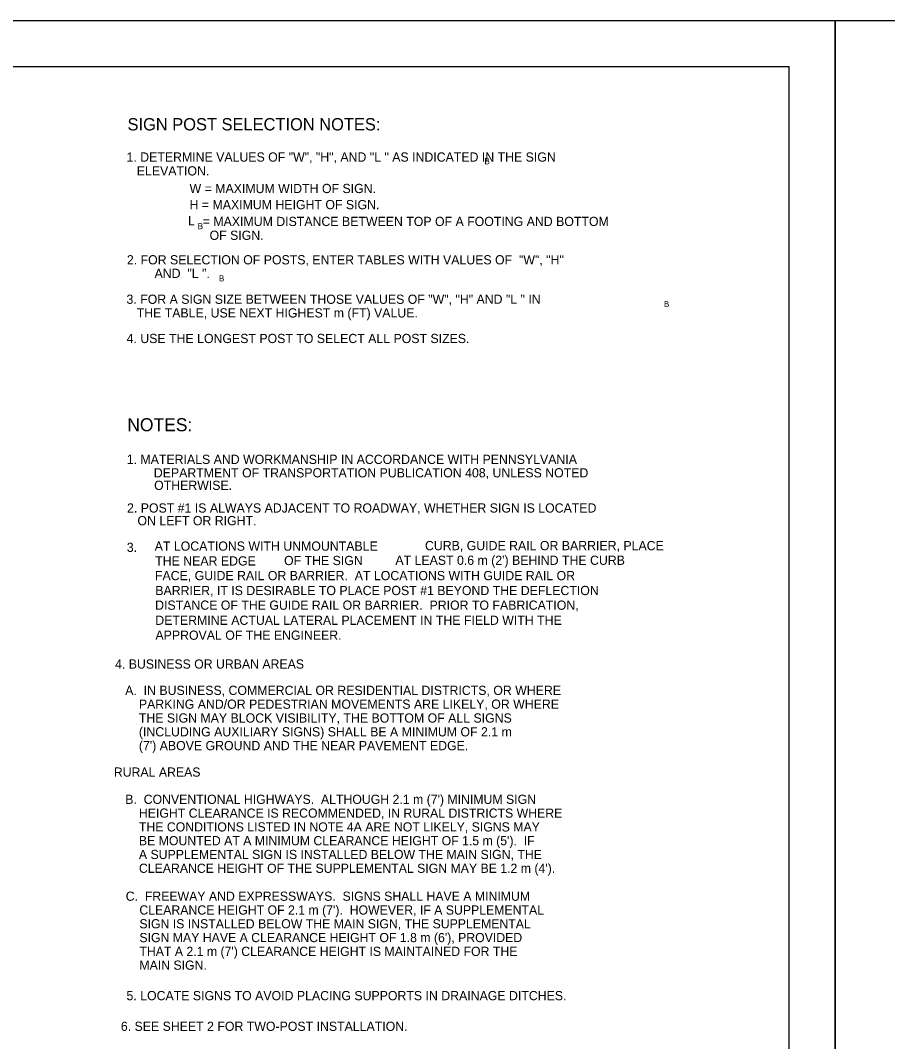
# Model space of a CAD drawing. Extents: x -1958 to 628, y -879 to 309.
# Drawn here: x -1382.9 to -1100.4, y -23.1 to 309.4 of the extents above; entities that cross this region are included whole.
import ezdxf

# ---------------------------------------------------------------- set-up
doc = ezdxf.new("R2010")
doc.units = 0
for name, color, linetype in [('1', 7, 'Continuous'), ('2', 7, 'Continuous'), ('4', 7, 'Continuous'), ('PLT-BNDY', 7, 'Continuous')]:
    doc.layers.add(name, color=color, linetype=linetype)

msp = doc.modelspace()

# ---------------------------------------------------------------- linework, layer by layer
at = {"layer": '1'}
for p in [(-1918.39, 294.44), (-1132.39, -269.56)]:
    msp.add_line(p, (-1132.39, 294.44), dxfattribs=at)
at = {"layer": 'PLT-BNDY'}
for points in [[(-1958.39, 309.44), (-1117.39, 309.44), (-1117.39, -284.56), (-1958.39, -284.56)], [(-1117.39, 309.44), (-276.39, 309.44), (-276.39, -284.56), (-1117.39, -284.56)]]:
    msp.add_lwpolyline(points, close=True, dxfattribs=at)

# ---------------------------------------------------------------- texts
at = {"layer": '1'}
for s, height, p in [('1. DETERMINE VALUES OF "W", "H", AND "L " AS INDICATED IN THE SIGN', 3, (-1348.3, 263.45)), ('B', 2, (-1231.7, 262.61)), ('   ELEVATION.', 3, (-1348.3, 258.95)), ('W = MAXIMUM WIDTH OF SIGN.', 3, (-1327.76, 253.21)), ('H = MAXIMUM HEIGHT OF SIGN.', 3, (-1327.76, 247.96)), ('L', 3, (-1328.26, 242.71)), ('B', 2, (-1325.14, 241.46)), (' = MAXIMUM DISTANCE BETWEEN TOP OF A FOOTING AND BOTTOM', 3, (-1324.59, 242.48)), ('   OF SIGN.', 3, (-1324.59, 237.98)), ('2. FOR SELECTION OF POSTS, ENTER TABLES WITH VALUES OF  "W", "H" ', 3, (-1348.18, 229.99)), ('AND  "L ".', 3, (-1339.17, 225.58)), ('B', 2, (-1318.22, 224.45)), ('3. FOR A SIGN SIZE BETWEEN THOSE VALUES OF "W", "H" AND "L " IN ', 3, (-1348.31, 217.15)), ('B', 2, (-1173.26, 216.11)), ('   THE TABLE, USE NEXT HIGHEST m (FT) VALUE.', 3, (-1348.34, 212.7)), ('4. USE THE LONGEST POST TO SELECT ALL POST SIZES.', 3, (-1348.27, 204.37)), ('1. MATERIALS AND WORKMANSHIP IN ACCORDANCE WITH PENNSYLVANIA', 3, (-1348.23, 165.01)), ('DEPARTMENT OF TRANSPORTATION PUBLICATION 408, UNLESS NOTED', 3, (-1339.41, 160.63)), ('OTHERWISE.', 3, (-1339.31, 156.56)), ('2. POST #1 IS ALWAYS ADJACENT TO ROADWAY, WHETHER SIGN IS LOCATED', 3, (-1348.13, 149.18)), ('   ON LEFT OR RIGHT.', 3, (-1348.08, 145.04)), ('AT LOCATIONS WITH UNMOUNTABLE', 3, (-1339.13, 136.76)), (' CURB, GUIDE RAIL OR BARRIER, PLACE ', 3, (-1252.19, 136.92)), ('3.', 3, (-1348.21, 136.37)), ('THE NEAR EDGE', 3, (-1338.96, 131.94)), ('OF THE SIGN ', 3, (-1296.98, 132.07)), ("AT LEAST 0.6 m (2') BEHIND THE CURB", 3, (-1260.71, 132.15)), ('FACE, GUIDE RAIL OR BARRIER.  AT LOCATIONS WITH GUIDE RAIL OR', 3, (-1339.04, 127.16)), ('BARRIER, IT IS DESIRABLE TO PLACE POST #1 BEYOND THE DEFLECTION ', 3, (-1338.92, 122.3)), ('DISTANCE OF THE GUIDE RAIL OR BARRIER.  PRIOR TO FABRICATION,', 3, (-1338.98, 117.53)), ('DETERMINE ACTUAL LATERAL PLACEMENT IN THE FIELD WITH THE', 3, (-1338.92, 112.62)), ('APPROVAL OF THE ENGINEER.', 3, (-1338.88, 107.75)), ('5. LOCATE SIGNS TO AVOID PLACING SUPPORTS IN DRAINAGE DITCHES.', 3, (-1348.31, -9.62)), (' 6. SEE SHEET 2 FOR TWO-POST INSTALLATION.', 3, (-1351.26, -19.6))]:
    msp.add_text(s, height=height, dxfattribs=at).set_placement(p)
at = {"layer": '2'}
for s, height, p in [('SIGN POST SELECTION NOTES:', 4.003, (-1347.98, 273.62)), ('NOTES:', 4.25, (-1348.04, 175.66))]:
    msp.add_text(s, height=height, dxfattribs=at).set_placement(p)
at = {"layer": '4'}
for s, height, p in [('  4. BUSINESS OR URBAN AREAS                                               ', 2.9895, (-1354.24, 98.37)), ('     A.  IN BUSINESS, COMMERCIAL OR RESIDENTIAL DISTRICTS, OR WHERE', 3, (-1354.31, 89.79)), ('         PARKING AND/OR PEDESTRIAN MOVEMENTS ARE LIKELY, OR WHERE', 3, (-1354.31, 85.29)), ('         THE SIGN MAY BLOCK VISIBILITY, THE BOTTOM OF ALL SIGNS', 3, (-1354.31, 80.79)), ('         (INCLUDING AUXILIARY SIGNS) SHALL BE A MINIMUM OF 2.1 m', 3, (-1354.31, 76.29)), ("         (7') ABOVE GROUND AND THE NEAR PAVEMENT EDGE.", 3, (-1354.31, 71.79)), ('       RURAL AREAS                                                           ', 2.9895, (-1360.2, 63.18)), ("     B.  CONVENTIONAL HIGHWAYS.  ALTHOUGH 2.1 m (7') MINIMUM SIGN", 2.9895, (-1354.26, 54.31)), ('         HEIGHT CLEARANCE IS RECOMMENDED, IN RURAL DISTRICTS WHERE', 2.9895, (-1354.26, 49.82)), ('         THE CONDITIONS LISTED IN NOTE 4A ARE NOT LIKELY, SIGNS MAY', 2.9895, (-1354.26, 45.33)), ("         BE MOUNTED AT A MINIMUM CLEARANCE HEIGHT OF 1.5 m (5').  IF", 2.9895, (-1354.26, 40.84)), ('         A SUPPLEMENTAL SIGN IS INSTALLED BELOW THE MAIN SIGN, THE', 2.9895, (-1354.26, 36.35)), ("         CLEARANCE HEIGHT OF THE SUPPLEMENTAL SIGN MAY BE 1.2 m (4').", 2.9895, (-1354.26, 31.86)), ('     C.  FREEWAY AND EXPRESSWAYS.  SIGNS SHALL HAVE A MINIMUM', 2.9895, (-1354.11, 22.76)), ("         CLEARANCE HEIGHT OF 2.1 m (7').  HOWEVER, IF A SUPPLEMENTAL", 2.9895, (-1354.11, 18.27)), ('         SIGN IS INSTALLED BELOW THE MAIN SIGN, THE SUPPLEMENTAL', 2.9895, (-1354.11, 13.78)), ("         SIGN MAY HAVE A CLEARANCE HEIGHT OF 1.8 m (6'), PROVIDED", 2.9895, (-1354.11, 9.29)), ("         THAT A 2.1 m (7') CLEARANCE HEIGHT IS MAINTAINED FOR THE", 2.9895, (-1354.11, 4.8)), ('         MAIN SIGN.', 2.9895, (-1354.11, 0.31))]:
    msp.add_text(s, height=height, dxfattribs=at).set_placement(p)

doc.saveas('drawing.dxf')
